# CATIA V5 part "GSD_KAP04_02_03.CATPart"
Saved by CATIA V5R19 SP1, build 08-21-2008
Part number: GSD_KAP04_02_03
Definition: Beispielmodell zum Kapitel 4 - Sketcher.
Description: CATIA V5 FLächenmodellierung  Copyright (c) 2009 Maik Hertha IT Consultants
Bounding box of the stored display mesh (mm): x -117.733 to 37.272, y 0 to 0, z -39.107 to 39.107
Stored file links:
  \GSD_BUCH_UEBUNG\GSD_KAP04_02_03.CATPart
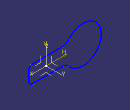
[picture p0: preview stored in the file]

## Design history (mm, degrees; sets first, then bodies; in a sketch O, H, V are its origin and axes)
AxisSystem1: origin (0, 0, 0), X (1, 0, 0), Y (0, 1, 0), Z (0, 0, 1)
Set1
  Sketch1 on zx-plane, origin (0, 0, 0), H (-1, 0, 0), V (0, 0, 1)
    line L1 (-32.2719, 18.1576) -> (33.3231, 18.1576)
    arc A1 centre (33.3231, 38.5091) radius 20.3514 from (33.3231, 18.1576) to (48.8294, 25.3282) ccw
    arc A2 centre (78.6263, 0) radius 39.1073 from (48.8294, 25.3282) to (48.1913, -24.5578) cw
    arc A3 centre (34.8032, -35.3605) radius 17.2029 from (48.1913, -24.5578) to (34.8032, -18.1576) ccw
    line L2 (34.8032, -18.1576) -> (-28.7989, -18.1576)
    arc A4 centre (-28.7989, -9.6846) radius 8.473 from (-28.7989, -18.1576) to (-37.2719, -9.6846) cw
    line L3 (-37.2719, -9.6846) -> (-37.2719, 13.1576)
    line L4 (-37.2719, 13.1576) -> (-32.2719, 18.1576)
    tangency: A1 A2, A1 L1, A3 A2, A3 L2, A4 L2, A4 L3
Body1 (main body)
